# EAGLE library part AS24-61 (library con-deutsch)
DEUTSCH Connector
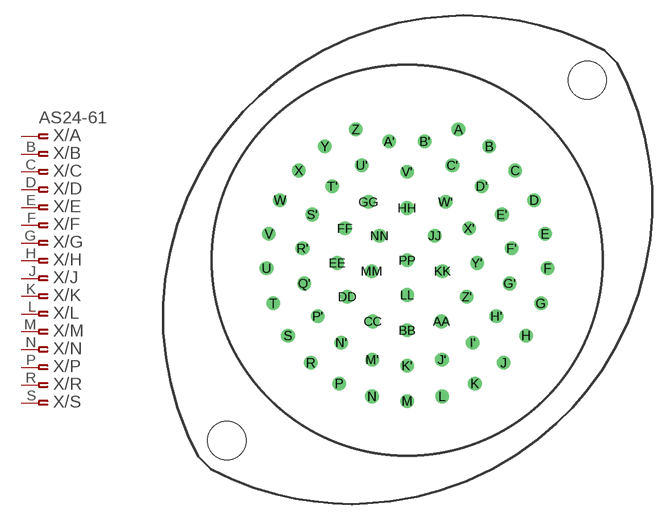
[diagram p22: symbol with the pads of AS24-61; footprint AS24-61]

Designator prefix X; gates /A=PINF_VAL /B=ASPINF /C=ASPINF /D=ASPINF /E=ASPINF /F=ASPINF /G=ASPINF /H=ASPINF /J=ASPINF /K=ASPINF /L=ASPINF /M=ASPINF /N=ASPINF /P=ASPINF /R=ASPINF /S=ASPINF /T=ASPINF /U=ASPINF /V=ASPINF /W=ASPINF /X=ASPINF /Y=ASPINF /Z=ASPINF /A'=PINF_VAL /B'=ASPINF /C'=ASPINF /D'=ASPINF /E'=ASPINF /F'=ASPINF /G'=ASPINF /H'=ASPINF /J'=ASPINF /K'=ASPINF /M'=ASPINF /N'=ASPINF /P'=ASPINF /R'=ASPINF /S'=ASPINF /T'=ASPINF /U'=ASPINF /V'=ASPINF /W'=ASPINF /X'=ASPINF /Y'=ASPINF /Z'=ASPINF /AA=PINF_VAL /BB=ASPINF /CC=ASPINF /DD=ASPINF /EE=ASPINF /FF=ASPINF /GG=ASPINF /HH=ASPINF /JJ=ASPINF /KK=ASPINF /LL=ASPINF /MM=ASPINF /NN=ASPINF /PP=ASPINF /I'=ASPINF /Q'=ASPINF

## AS24-61 (OC_FARNELL: unknown; OC_NEWARK: unknown)  [AS24-61]
A  /A:1  pas
A'  /A':1  pas
AA  /AA:1  pas
B  /B:1  pas
B'  /B':1  pas
BB  /BB:1  pas
C  /C:1  pas
C'  /C':1  pas
CC  /CC:1  pas
D  /D:1  pas
D'  /D':1  pas
DD  /DD:1  pas
E  /E:1  pas
E'  /E':1  pas
EE  /EE:1  pas
F  /F:1  pas
F'  /F':1  pas
FF  /FF:1  pas
G  /G:1  pas
G'  /G':1  pas
GG  /GG:1  pas
H  /H:1  pas
H'  /H':1  pas
HH  /HH:1  pas
I'  /I':1  pas
J  /J:1  pas
J'  /J':1  pas
JJ  /JJ:1  pas
K  /K:1  pas
K'  /K':1  pas
KK  /KK:1  pas
L  /L:1  pas
LL  /LL:1  pas
M  /M:1  pas
M'  /M':1  pas
MM  /MM:1  pas
N  /N:1  pas
N'  /N':1  pas
NN  /NN:1  pas
P  /P:1  pas
P'  /P':1  pas
PP  /PP:1  pas
Q'  /Q':1  pas
R  /R:1  pas
R'  /R':1  pas
S  /S:1  pas
S'  /S':1  pas
T  /T:1  pas
T'  /T':1  pas
U  /U:1  pas
U'  /U':1  pas
V  /V:1  pas
V'  /V':1  pas
W  /W:1  pas
W'  /W':1  pas
X  /X:1  pas
X'  /X':1  pas
Y  /Y:1  pas
Y'  /Y':1  pas
Z  /Z:1  pas
Z'  /Z':1  pas

## Footprint AS24-61 (pad centres in mm)
DEUTSCH Connector
drill 0.813 round: A 4.978,12.7; A' -1.727,11.532; AA 3.327,-5.918; B 7.976,11.049; B' 1.727,11.532; BB 0,-6.782; C 10.49,8.712; C' 4.394,9.22; CC -3.327,-5.918; D 12.319,5.842; D' 7.239,7.188; DD -5.791,-3.531; E 13.386,2.565; E' 9.195,4.445; EE -6.782,-0.254; F 13.614,-0.762; F' 10.135,1.168; FF -6.02,3.099; G 12.979,-4.166; G' 9.957,-2.235; GG -3.734,5.664; H 11.532,-7.29; H' 8.661,-5.41; HH 0,5.08; I' 6.375,-7.976; J 9.347,-9.931; J' 3.378,-9.627; JJ 2.667,2.388; K 6.579,-11.938; K' 0,-10.211; KK 3.429,-1.041; L 3.404,-13.183; LL 0,-3.353; M 0,-13.64; M' -3.378,-9.627; MM -3.429,-1.041; N -3.404,-13.183; N' -6.375,-7.976; NN -2.667,2.388; P -6.579,-11.938; P' -8.661,-5.41; PP 0,0; Q' -9.957,-2.235; R -9.347,-9.931; R' -10.135,1.168; S -11.532,-7.29; S' -9.195,4.445; T -12.979,-4.166; T' -7.239,7.188; U -13.614,-0.762; U' -4.394,9.22; V -13.386,2.565; V' 0,8.585; W -12.319,5.842; W' 3.734,5.664; X -10.49,8.712; X' 6.02,3.099; Y -7.976,11.049; Y' 6.782,-0.254; Z -4.978,12.7; Z' 5.791,-3.531
hole 3.7 at -17.462,-17.462
hole 3.7 at 17.462,17.462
